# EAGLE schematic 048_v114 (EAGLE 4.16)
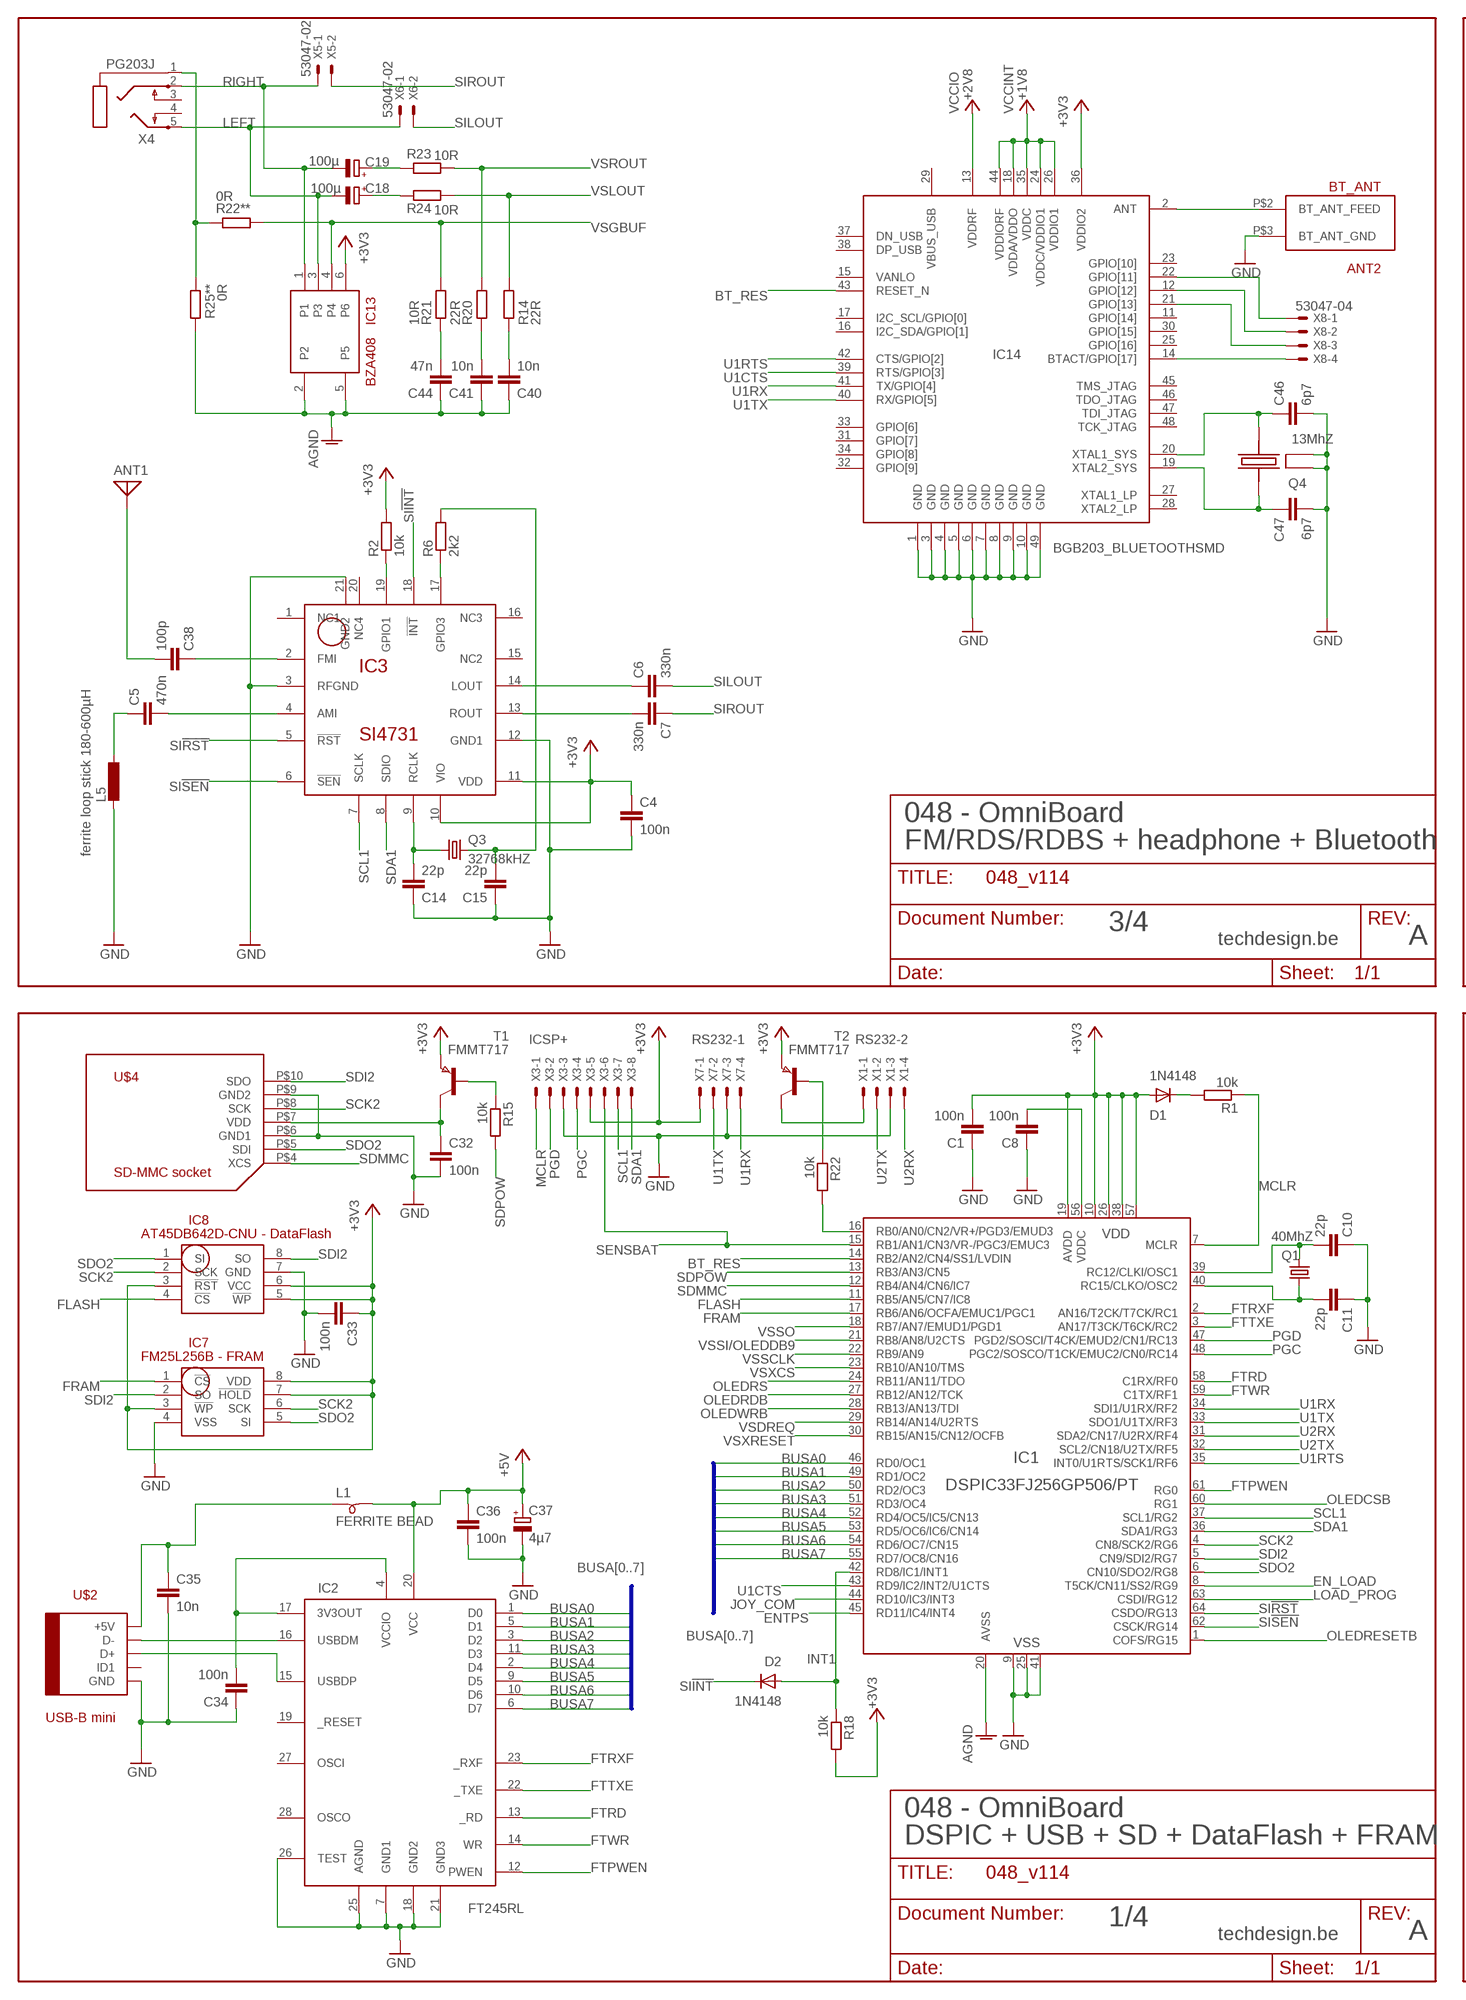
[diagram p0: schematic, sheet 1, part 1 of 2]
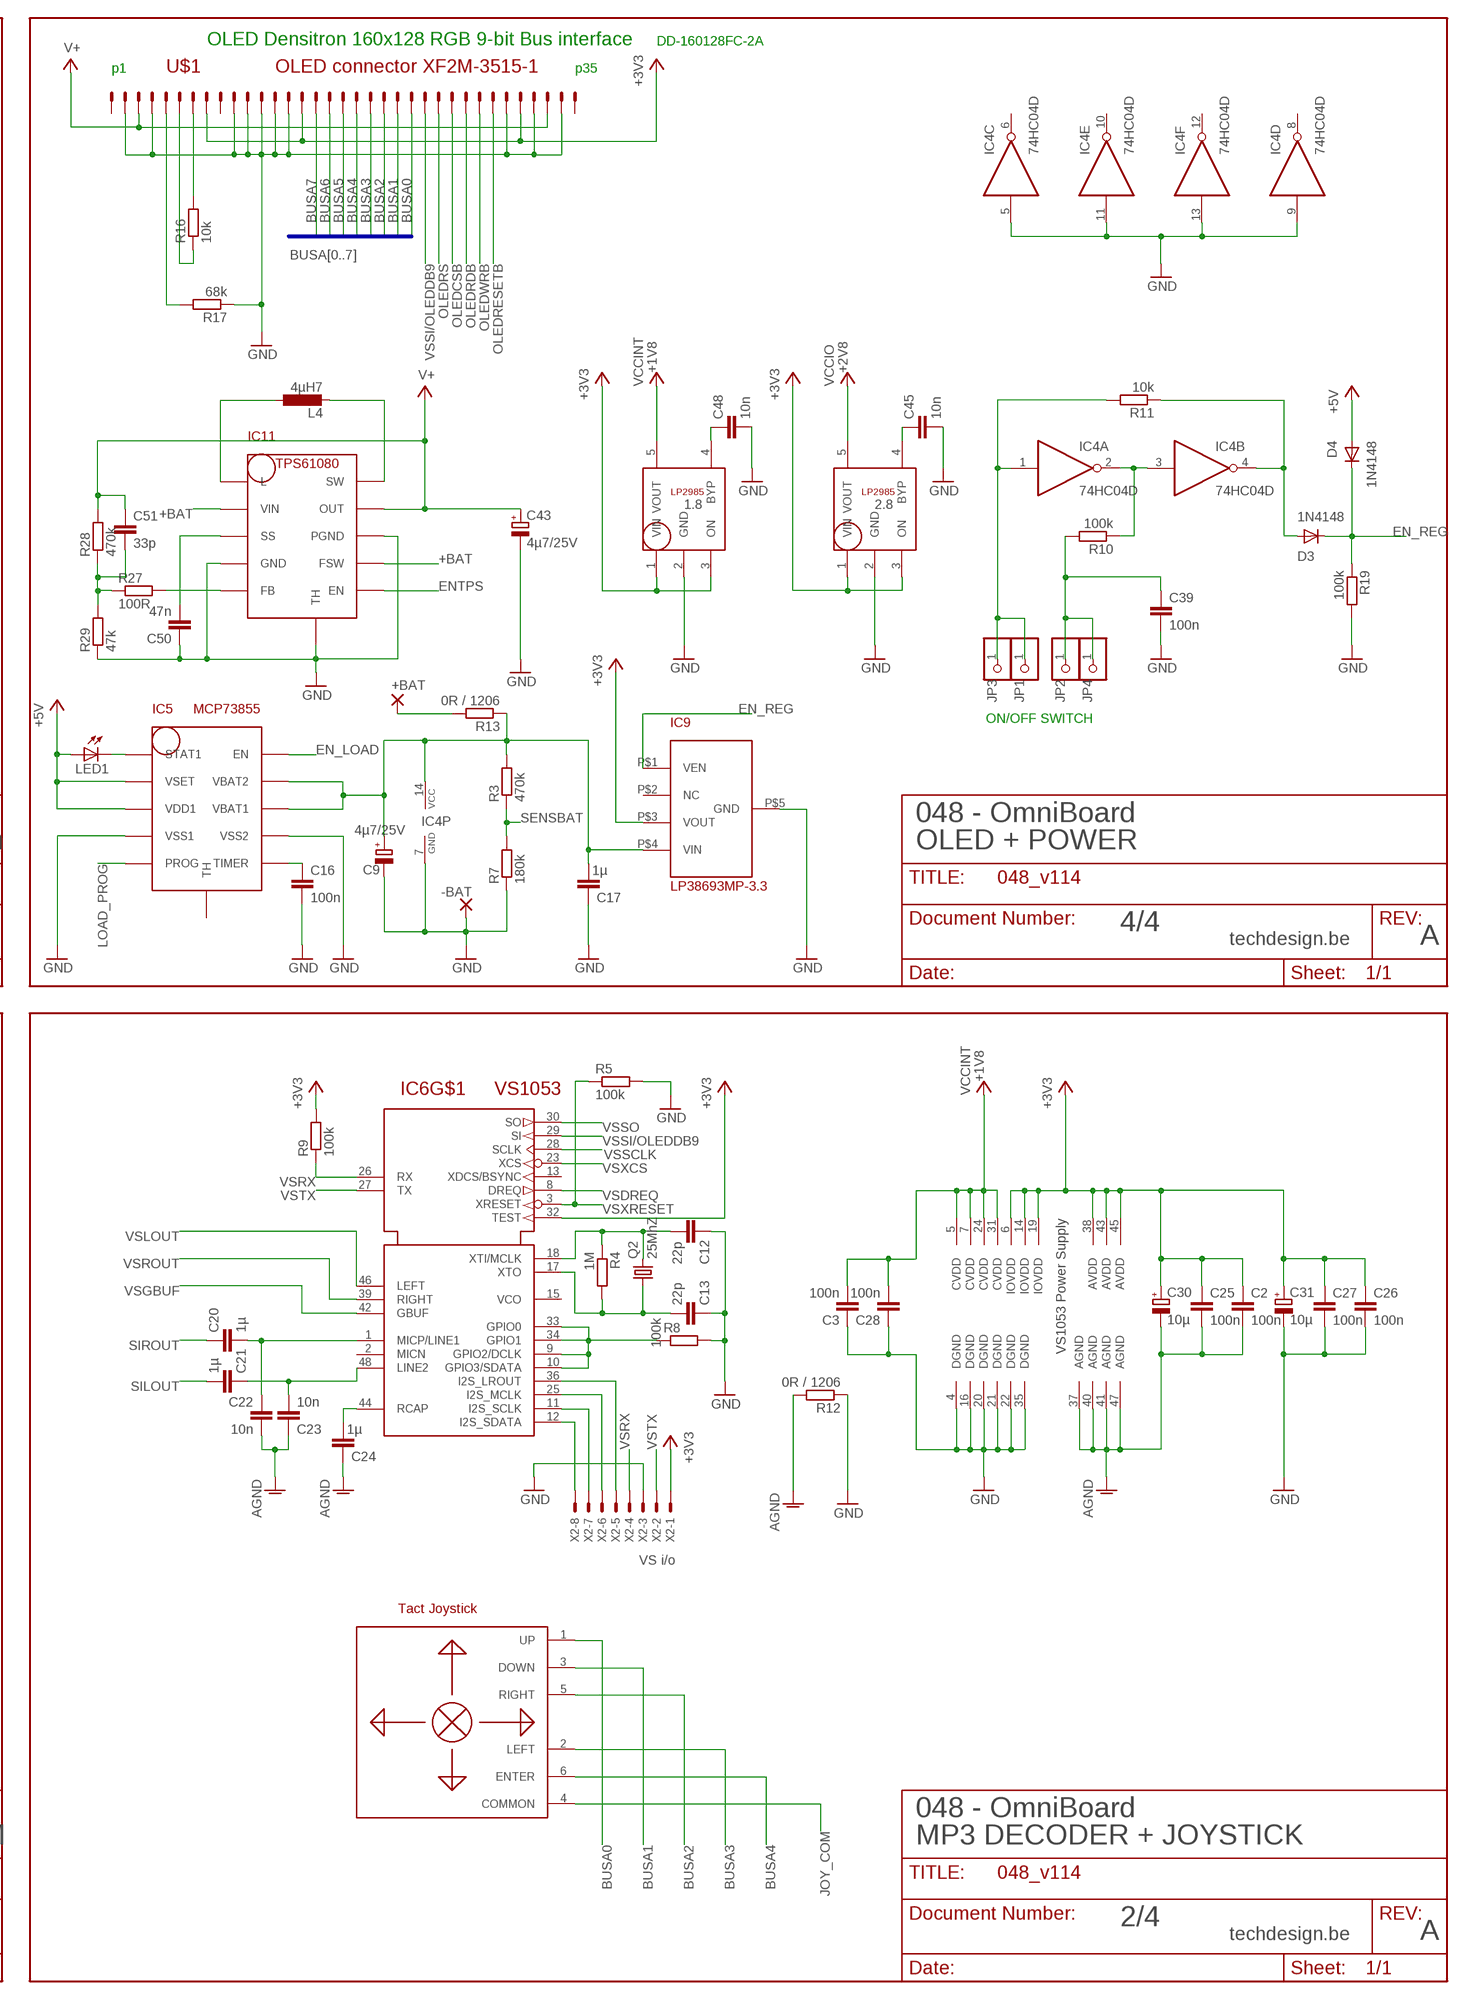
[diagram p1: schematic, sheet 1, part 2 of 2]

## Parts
+BAT  2,54/0,8  [2,54/0,8]
-BAT  2,54/0,8  [2,54/0,8]
ANT1  ANTENNA  [PAD-01]
ANT2  BT_ANT  [BTANT_PAC]
C1  100n  C-EUC0402  [C0402]
C2  100n  C-EUC0603  [C0603]
C3  100n  C-EUC0603  [C0603]
C4  100n  C-EUC0603  [C0603]
C5  470n  C-EUC0603  [C0603]
C6  330n  C-EUC0603  [C0603]
C7  330n  C-EUC0603  [C0603]
C8  100n  C-EUC0402  [C0402]
C9  4µ7/25V  CPOL-EUB/3528-21R  [B/3528-21R]
C10  22p  C-EUC0402  [C0402]
C11  22p  C-EUC0402  [C0402]
C12  22p  C-EUC0402  [C0402]
C13  22p  C-EUC0402  [C0402]
C14  22p  C-EUC0402  [C0402]
C15  22p  C-EUC0402  [C0402]
C16  100n  C-EUC0603  [C0603]
C17  1µ  C-EUC0603  [C0603]
C18  100µ  CPOL-EUE2-5  [E2-5]
C19  100µ  CPOL-EUE2-5  [E2-5]
C20  1µ  C-EUC0603  [C0603]
C21  1µ  C-EUC0603  [C0603]
C22  10n  C-EUC0603  [C0603]
C23  10n  C-EUC0603  [C0603]
C24  1µ  C-EUC0603  [C0603]
C25  100n  C-EUC0603  [C0603]
C26  100n  C-EUC0603  [C0603]
C27  100n  C-EUC0603  [C0603]
C28  100n  C-EUC0603  [C0603]
C30  10µ  CPOL-EUB/3528-21R  [B/3528-21R]
C31  10µ  CPOL-EUB/3528-21R  [B/3528-21R]
C32  100n  C-EUC0402  [C0402]
C33  100n  C-EUC0402  [C0402]
C34  100n  C-EUC0402  [C0402]
C35  10n  C-EUC0402  [C0402]
C36  100n  C-EUC0402  [C0402]
C37  4µ7  CPOL-EUB/3528-21R  [B/3528-21R]
C38  100p  C-EUC0402  [C0402]
C39  100n  C-EUC0603  [C0603]
C40  10n  C-EUC0603  [C0603]
C41  10n  C-EUC0603  [C0603]
C43  4µ7/25V  CPOL-EUB/3528-21R  [B/3528-21R]
C44  47n  C-EUC0603  [C0603]
C45  10n  C-EUC0402  [C0402]
C46  6p7  C-EUC0402  [C0402]
C47  6p7  C-EUC0402  [C0402]
C48  10n  C-EUC0402  [C0402]
C50  47n  C-EUC0603  [C0603]
C51  33p  C-EUC0402  [C0402]
D1  1N4148  PMLL4150  [SOD80C]
D2  1N4148  PMLL4150  [SOD80C]
D3  1N4148  PMLL4150  [SOD80C]
D4  1N4148  PMLL4150  [SOD80C]
IC1  DSPIC33FJ256GP506/PT  [TQFP64-10X10]
IC2  FT245RL  [SSOP28DB]
IC3  SI4731  [QFN20-3X3]
IC4  74HC04D  [SO14]
IC5  MCP73855  [QFN10-3X3]
IC6  VS1053  [LQFP-48]
IC7  FM25L256B - FRAM  FM25-FRAM  [SO-8]
IC8  AT45DB642D-CNU - DataFlash  AT45DB041B-SU  [SO-8W]
IC9  LP38693MP-3.3  [SOT223-5]
IC10  LP2985IM5-1.8  LP2985IM5-2.5  [SOT23-5]
IC11  TPS61080  [QFN10-3X3]
IC12  LP2985IM5-2.8  LP2985IM5-2.5  [SOT23-5]
IC13  BZA408  [SOT-457]
IC14  BGB203_BLUETOOTHSMD  [BGB203]
JP1  PINHD-1X1  [1X01]
JP2  PINHD-1X1  [1X01]
JP3  PINHD-1X1  [1X01]
JP4  PINHD-1X1  [1X01]
L1  FERRITE BEAD  SM-B5  [SM-B5]
L4  4µH7  L-EUL5650M  [L5650M]
L5  ferrite loop stick 180-600µH  L-EU0204/7  [0204/7]
LED1  LEDCHIP-LED0805  [CHIP-LED0805]
Q1  40MhZ  CRYSTALHC49S  [HC49/S]
Q2  25MhZ  CRYSTALHC49S  [HC49/S]
Q3  32768kHZ  CRYSTALTC26H  [TC26H]
Q4  13MhZ  X_ABM3B  [X-ABM3B_PACK]
R1  10k  R-EU_R0402  [R0402]
R2  10k  R-EU_R0402  [R0402]
R3  470k  R-EU_R0402  [R0402]
R4  1M  R-EU_R0402  [R0402]
R5  100k  R-EU_R0402  [R0402]
R6  2k2  R-EU_R0402  [R0402]
R7  180k  R-EU_R0402  [R0402]
R8  100k  R-EU_R0402  [R0402]
R9  100k  R-EU_R0402  [R0402]
R10  100k  R-EU_R0402  [R0402]
R11  10k  R-EU_R0402  [R0402]
R12  0R / 1206  R-EU_R0805  [R0805]
R13  0R / 1206  R-EU_R1206  [R1206]
R14  22R  R-EU_R0402  [R0402]
R15  10k  R-EU_R0402  [R0402]
R16  10k  R-EU_R0402  [R0402]
R17  68k  R-EU_R0402  [R0402]
R18  10k  R-EU_R0402  [R0402]
R19  100k  R-EU_R0402  [R0402]
R20  22R  R-EU_R0402  [R0402]
R21  10R  R-EU_R0402  [R0402]
R22  10k  R-EU_R0402  [R0402]
R22**  0R  R-EU_R0805  [R0805]
R23  10R  R-EU_R0402  [R0402]
R24  10R  R-EU_R0402  [R0402]
R25**  0R  R-EU_R0805  [R0805]
R27  100R  R-EU_R0402  [R0402]
R28  470k  R-EU_R0402  [R0402]
R29  47k  R-EU_R0402  [R0402]
T1  FMMT717  [SOT-23]
T2  FMMT717  [SOT-23]
U$1  OLED connector XF2M-3515-1  XF2M-3515-1  [XF2M-PAC]
U$2  USB-B mini  USB-MINI-B-TH2TH4  [USB-MINI-B-TH4]
U$3  TACT2_DEV  [TACT2_PACK]
U$4  SD-MMC socket  SD-MMC-3  [MMC-SD-PACK3]
X1  RS232-2  53047-04  [53047-04]
X2  VS i/o  53047-08  [53047-08]
X3  ICSP+  53047-08  [53047-08]
X4  PG203J  [PG203J]
X5  53047-02  [53047-02]
X6  53047-02  [53047-02]
X7  RS232-1  53047-04  [53047-04]
X8  53047-04  [53047-04]

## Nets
+3V3: C1.2 C2.1 C4.1 C25.1 C26.1 C27.1 C30.+ C31.+ C33.1 D1.A IC1.10(VDD) IC1.19(AVDD) IC1.26(VDD) IC1.38(VDD) IC1.57(VDD) IC3.10(VIO) IC3.11(VDD) IC6.6(IOVDD) IC6.14(IOVDD) IC6.19(IOVDD) IC6.32(TEST) IC6.38(AVDD) IC6.43(AVDD) IC6.45(AVDD) IC7.3(!WP) IC7.7(!HOLD) IC7.8(VDD) IC8.3(!RST) IC8.5(!WP) IC8.6(VCC) IC9.P$3(VOUT) IC10.1(VIN) IC10.3(ON) IC12.1(VIN) IC12.3(ON) IC13.6 IC14.36(VDDIO2) R2.2 R9.2 R18.2 T1.2(E) T2.2(E) U$1.8 U$1.15 U$1.31 X2.1 X3.5 X7.1
+5V: C36.1 C37.+ D4.A IC2.20(VCC) IC5.2(VSET) IC5.3(VDD1) L1.2 LED1.A
+BAT: C9.+ C17.2 IC4.14(P:VCC) IC5.8(VBAT1) IC5.9(VBAT2) IC9.P$4(VIN) IC11.2(VIN) IC11.7(FSW) R3.2 R13.1
AGND: C2.2 C22.2 C23.1 C24.1 C25.2 C30.- C40.1 C41.1 C44.1 IC1.20(AVSS) IC6.37(AGND) IC6.40(AGND) IC6.41(AGND) IC6.47(AGND) IC13.2 IC13.5 R12.2 R25**.2
BT_RES: IC1.14(RB2/AN2/CN4/SS1/LVDIN) IC14.43(RESET_N)
BUSA0: IC1.46(RD0/OC1) IC2.1(D0) U$1.23 U$3.1(UP)
BUSA1: IC1.49(RD1/OC2) IC2.5(D1) U$1.22 U$3.3(DOWN)
BUSA2: IC1.50(RD2/OC3) IC2.3(D2) U$1.21 U$3.5(RIGHT)
BUSA3: IC1.51(RD3/OC4) IC2.11(D3) U$1.20 U$3.2(LEFT)
BUSA4: IC1.52(RD4/OC5/IC5/CN13) IC2.2(D4) U$1.19 U$3.6(ENTER)
BUSA5: IC1.53(RD5/OC6/IC6/CN14) IC2.9(D5) U$1.18
BUSA6: IC1.54(RD6/OC7/CN15) IC2.10(D6) U$1.17
BUSA7: IC1.55(RD7/OC8/CN16) IC2.6(D7) U$1.16
EN_LOAD: IC1.8(T5CK/CN11/SS2/RG9) IC5.10(EN)
EN_REG: D3.C D4.C IC9.P$1(VEN) R19.1
ENTPS: IC1.45(RD11/IC4/INT4) IC11.6(EN)
FLASH: IC1.11(RB5/AN5/CN7/IC8) IC8.4(!CS)
FRAM: IC1.17(RB6/AN6/OCFA/EMUC1/PGC1) IC7.1(!CS)
FTPWEN: IC1.61(RG0) IC2.12(PWEN)
FTRD: IC1.58(C1RX/RF0) IC2.13(_RD)
FTRXF: IC1.2(AN16/T2CK/T7CK/RC1) IC2.23(_RXF)
FTTXE: IC1.3(AN17/T3CK/T6CK/RC2) IC2.22(_TXE)
FTWR: IC1.59(C1TX/RF1) IC2.14(WR)
GND: -BAT.1(P) ANT2.P$3(BT_ANT_GND) C1.1 C3.1 C4.2 C8.1 C9.- C10.1 C11.1 C12.1 C13.1 C14.1 C15.1 C16.2 C17.1 C26.2 C27.2 C28.1 C31.- C32.2 C33.2 C34.1 C35.2 C36.2 C37.- C39.2 C43.- C45.2 C46.2 C47.2 C48.2 C50.1 IC1.9(VSS) IC1.25(VSS) IC1.41(VSS) IC2.7(GND1) IC2.18(GND2) IC2.21(GND3) IC2.25(AGND) IC2.26(TEST) IC3.3(RFGND) IC3.12(GND1) IC3.21(GND2) IC4.5(C:I) IC4.7(P:GND) IC4.9(D:I) IC4.11(E:I) IC4.13(F:I) IC5.4(VSS1) IC5.7(VSS2) IC6.4(DGND) IC6.16(DGND) IC6.20(DGND) IC6.21(DGND) IC6.22(DGND) IC6.35(DGND) IC7.4(VSS) IC8.7(GND) IC9.P$5(GND) IC10.2(GND) IC11.4(GND) IC11.8(PGND) IC11.P$1(TH) IC12.2(GND) IC14.1(GND) IC14.3(GND) IC14.4(GND) IC14.5(GND) IC14.6(GND) IC14.7(GND) IC14.8(GND) IC14.9(GND) IC14.10(GND) IC14.49(GND) L5.2 Q4.P$2 Q4.P$4 R5.2 R7.1 R8.2 R12.1 R17.1 R19.2 R29.1 U$1.2 U$1.4 U$1.10 U$1.11 U$1.12 U$1.13 U$1.14 U$1.30 U$1.32 U$1.34 U$2.P$5(GND) U$4.P$6(GND1) U$4.P$9(GND2) X1.3 X2.3 X3.3 X7.3
INT1: D2.A IC1.42(RD8/IC1/INT1) R18.1
JOY_COM: IC1.44(RD10/IC3/INT3) U$3.4(COMMON)
LEFT: C18.- IC13.3 X4.5 X6.1
LOAD_PROG: IC1.63(CSDI/RG12) IC5.5(PROG)
MCLR: IC1.7(MCLR) R1.1 X3.1
N$1: IC6.12(I2S_SDATA) X2.8
N$2: C10.2 IC1.39(RC12/CLKI/OSC1) Q1.2
N$3: C6.1 IC3.14(LOUT)
N$4: IC6.11(I2S_SCLK) X2.7
N$5: C7.2 IC3.13(ROUT)
N$6: C5.2 IC3.4(AMI)
N$7: IC6.25(I2S_MCLK) X2.6
N$8: C35.1 L1.1 U$2.P$1(+5V)
N$9: IC3.19(GPIO1) R2.1
N$10: C5.1 L5.1
N$11: D1.C R1.2
N$12: C11.2 IC1.40(RC15/CLKO/OSC2) Q1.1
N$13: C34.2 IC2.4(VCCIO) IC2.17(3V3OUT)
N$14: C12.2 IC6.18(XTI/MCLK) Q2.2 R4.1
N$15: C13.2 IC6.17(XTO) Q2.1 R4.2
N$16: C39.1 JP2.1 JP4.1 R10.2
N$17: C20.2 C22.1 IC6.1(MICP/LINE1)
N$18: IC3.17(GPIO3) R6.1
N$19: C38.1 IC3.2(FMI)
N$20: ANT1.1 C38.2
N$21: IC5.1(STAT1) LED1.C
N$22: R16.1 U$1.6
N$23: D3.A IC4.4(B:O) R11.1
N$24: C14.2 IC3.9(RCLK) Q3.1
N$25: C15.2 Q3.2 R6.2
N$26: C21.1 C23.2 IC6.48(LINE2)
N$27: C8.2 IC1.56(VDDC)
N$28: C16.1 IC5.6(TIMER)
N$29: IC6.9(GPIO2/DCLK) IC6.10(GPIO3/SDATA) IC6.33(GPIO0) IC6.34(GPIO1) R8.1
N$30: IC6.36(I2S_LROUT) X2.5
N$31: R16.2 U$1.7
N$32: C24.2 IC6.44(RCAP)
N$33: R17.2 U$1.5
N$35: +BAT.1(P) R13.2
N$36: C32.1 T1.1(C) U$4.P$7(VDD)
N$37: IC4.2(A:O) IC4.3(B:I) R10.1
N$38: IC4.1(A:I) JP1.1 JP3.1 R11.2
N$39: R15.1 T1.3(B)
N$40: IC2.16(USBDM) U$2.P$2(D-)
N$41: IC2.15(USBDP) U$2.P$3(D+)
N$42: R22**.1 R25**.1 X4.1
N$43: C48.1 IC10.4(BYP)
N$44: IC14.14(BTACT/GPIO[17]) X8.4
N$45: C40.2 R14.1
N$46: C41.2 R20.1
N$47: IC11.1(L) L4.1
N$48: C19.+ R23.1
N$49: C18.+ R24.1
N$50: IC11.10(SW) L4.2
N$51: C45.1 IC12.4(BYP)
N$52: C44.2 R21.1
N$53: C50.2 IC11.3(SS)
N$54: IC14.22(GPIO[11]) X8.1
N$55: IC11.5(FB) R27.2
N$56: C51.2 R27.1 R28.1 R29.2
N$57: IC14.12(GPIO[12]) X8.2
N$58: IC14.21(GPIO[13]) X8.3
N$60: ANT2.P$2(BT_ANT_FEED) IC14.2(ANT)
N$61: C46.1 IC14.20(XTAL1_SYS) Q4.P$3
N$62: C47.1 IC14.19(XTAL2_SYS) Q4.P$1
N$63: R22.1 T2.3(B)
N$64: IC1.16(RB0/AN0/CN2/VR+/PGD3/EMUD3) R22.2
N$65: T2.1(C) X1.1
OLEDCSB: IC1.60(RG1) U$1.26
OLEDRDB: IC1.27(RB12/AN12/TCK) U$1.27
OLEDRESETB: IC1.1(COFS/RG15) U$1.29
OLEDRS: IC1.24(RB11/AN11/TDO) U$1.25
OLEDWRB: IC1.28(RB13/AN13/TDI) U$1.28
PGC: IC1.48(PGC2/SOSCO/T1CK/EMUC2/CN0/RC14) X3.4
PGD: IC1.47(PGD2/SOSCI/T4CK/EMUD2/CN1/RC13) X3.2
RIGHT: C19.- IC13.1 X4.2 X5.1
SCK2: IC1.4(CN8/SCK2/RG6) IC7.6(SCK) IC8.2(SCK) U$4.P$8(SCK)
SCL1: IC1.37(SCL1/RG2) IC3.7(SCLK) X3.7
SDA1: IC1.36(SDA1/RG3) IC3.8(SDIO) X3.8
SDI2: IC1.5(CN9/SDI2/RG7) IC7.2(SO) IC8.8(SO) U$4.P$10(SDO)
SDMMC: IC1.12(RB4/AN4/CN6/IC7) U$4.P$4(XCS)
SDO2: IC1.6(CN10/SDO2/RG8) IC7.5(SI) IC8.1(SI) U$4.P$5(SDI)
SDPOW: IC1.13(RB3/AN3/CN5) R15.2
SENSBAT: IC1.15(RB1/AN1/CN3/VR-/PGC3/EMUC3) R3.1 R7.2 X3.6
SI!INT: D2.C IC3.18(!INT)
SI!RST: IC1.64(CSDO/RG13) IC3.5(!RST)
SI!SEN: IC1.62(CSCK/RG14) IC3.6(!SEN)
SILOUT: C6.2 C21.2 X6.2
SIROUT: C7.1 C20.1 X5.2
U1CTS: IC1.43(RD9/IC2/INT2/U1CTS) IC14.39(RTS/GPIO[3])
U1RTS: IC1.35(INT0/U1RTS/SCK1/RF6) IC14.42(CTS/GPIO[2])
U1RX: IC1.34(SDI1/U1RX/RF2) IC14.41(TX/GPIO[4]) X7.4
U1TX: IC1.33(SDO1/U1TX/RF3) IC14.40(RX/GPIO[5]) X7.2
U2RX: IC1.31(SDA2/CN17/U2RX/RF4) X1.4
U2TX: IC1.32(SCL2/CN18/U2TX/RF5) X1.2
V+: C43.+ C51.1 IC11.9(OUT) R28.2 U$1.3 U$1.33
VCCINT: C3.2 C28.2 IC6.5(CVDD) IC6.7(CVDD) IC6.24(CVDD) IC6.31(CVDD) IC10.5(VOUT) IC14.18(VDDA/VDDO) IC14.24(VDDC/VDDIO1) IC14.26(VDDIO1) IC14.35(VDDC) IC14.44(VDDIORF)
VCCIO: IC12.5(VOUT) IC14.13(VDDRF)
VSDREQ: IC1.29(RB14/AN14/U2RTS) IC6.8(DREQ)
VSGBUF: IC6.42(GBUF) IC13.4 R21.2 R22**.2
VSLOUT: IC6.46(LEFT) R14.2 R24.2
VSROUT: IC6.39(RIGHT) R20.2 R23.2
VSRX: IC6.26(RX) R9.1 X2.4
VSSCLK: IC1.22(RB9/AN9) IC6.28(SCLK)
VSSI/OLEDDB9: IC1.21(RB8/AN8/U2CTS) IC6.29(SI) U$1.24
VSSO: IC1.18(RB7/AN7/EMUD1/PGD1) IC6.30(SO)
VSTX: IC6.27(TX) X2.2
VSXCS: IC1.23(RB10/AN10/TMS) IC6.23(XCS)
VSXRESET: IC1.30(RB15/AN15/CN12/OCFB) IC6.3(XRESET) R5.1
Unconnected: IC2.19(_RESET) IC2.27(OSCI) IC2.28(OSCO) IC3.1(NC1) IC3.15(NC2) IC3.16(NC3) IC3.20(NC4) IC4.6(C:O) IC4.8(D:O) IC4.10(E:O) IC4.12(F:O) IC5.P$1(TH) IC6.2(MICN) IC6.13(XDCS/BSYNC) IC6.15(VCO) IC9.P$2(NC) IC14.11(GPIO[14]) IC14.15(VANLO) IC14.16(I2C_SDA/GPIO[1]) IC14.17(I2C_SCL/GPIO[0]) IC14.23(GPIO[10]) IC14.25(GPIO[16]) IC14.27(XTAL1_LP) IC14.28(XTAL2_LP) IC14.29(VBUS_USB) IC14.30(GPIO[15]) IC14.31(GPIO[7]) IC14.32(GPIO[9]) IC14.33(GPIO[6]) IC14.34(GPIO[8]) IC14.37(DN_USB) IC14.38(DP_USB) IC14.45(TMS_JTAG) IC14.46(TDO_JTAG) IC14.47(TDI_JTAG) IC14.48(TCK_JTAG) U$1.1 U$1.9 U$1.35 U$2.P$4(ID1) X4.3 X4.4

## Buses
BUSA[0..7]

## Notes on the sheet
- OLED Densitron 160x128 RGB 9-bit Bus interface | DD-160128FC-2A
- p1 | p35
- +2V8 | +1V8
- +1V8 | +2V8
- 1.8 | 2.8
- ON/OFF SWITCH
- 048 - OmniBoard | 048 - OmniBoard
- FM/RDS/RDBS + headphone + Bluetooth | OLED + POWER
- 3/4 | 4/4
- techdesign.be | A | techdesign.be | A
- +1V8
- 048 - OmniBoard | 048 - OmniBoard
- DSPIC + USB + SD + DataFlash + FRAM | MP3 DECODER + JOYSTICK
- 1/4 | 2/4
- techdesign.be | A | techdesign.be | A

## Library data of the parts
+BAT -BAT = wirepad:2,54/0,8: THROUGH-HOLE PAD
ANT1 = discrete:ANTENNA
ANT2 = 048:BT_ANT
C1-C8 C10-C17 C20-C28 C32-C36 C38-C41 C44-C48 C50 C51 = rcl:C-EU: CAPACITOR, European symbol
C9 C18 C19 C30 C31 C37 C43 = rcl:CPOL-EU: POLARIZED CAPACITOR, European symbol
D1-D4 = diode:PMLL4150: DIODE
IC1 = microchip-dspic:DSPIC33FJ256GP506: dsPIC33 General DSC with CAN and CoDec ports
IC2 = ftdichip-2:FT245RL: USB FIFO Controller 4th Generation USB Controller (USB <-> Parallel) - FIFO
IC3 = 048:SI4731
IC4 = 74xx-eu:74*04: Hex INVERTER
IC5 = 048:MCP73855
IC6 = vs1053:VS1053
IC7 = 044:FM25-FRAM
IC8 = 044:AT45DB041B-SU
IC9 = 550:LP38693MP-3.3
IC10 IC12 = 031:LP2985IM5-2.5
IC11 = 048:TPS61080
IC13 = 048:BZA408
IC14 = SparkFun-3-2-07:BGB203_BLUETOOTH
JP1-JP4 = pinhead:PINHD-1X1: PIN HEADER
L1 = inductor-neosid:SM-B: INDUCTOR
L4 L5 = rcl:L-EU: INDUCTOR, European symbol
LED1 = led:LED: LED
Q1-Q3 = crystal:CRYSTAL: CRYSTAL
Q4 = 536:X_ABM3B
R1-R22 R22** R23 R24 R25** R27-R29 = rcl:R-EU_: RESISTOR, European symbol
T1 T2 = zetex:FMMT7*: PNP SILICON POWER (SWITCHING) TRANSISTORS SuperSOT Source: http://www.zetex.com/3.0/pdf/FMMT717.pdf
U$1 = 048:XF2M-3515-1
U$2 = 031:USB-MINI-B-TH2
U$3 = tact-smt:TACT2_DEV
U$4 = 031:SD-MMC-3
X1 X7 X8 = con-molex:53?-04: CONNECTOR wire to board 1.25 mm (.049 inch) pitch header
X2 X3 = con-molex:53?-08: CONNECTOR wire to board 1.25 mm (.049 inch) pitch header
X4 = con-hirschmann:PG203J: MIC/HEADPHONE JACK KS-S stereo microphone/headphone jack PG203JN (Schukat)
X5 X6 = con-molex:53?-02: CONNECTOR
